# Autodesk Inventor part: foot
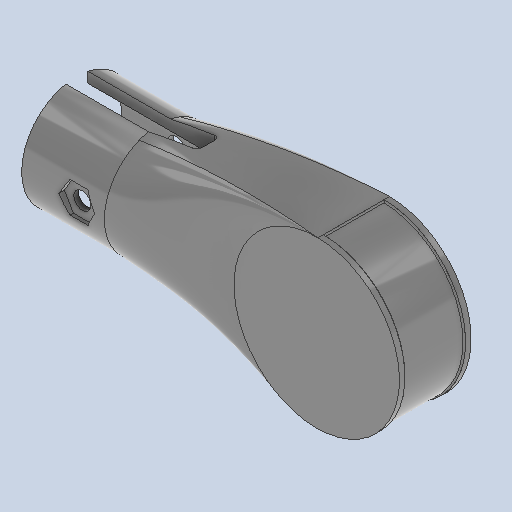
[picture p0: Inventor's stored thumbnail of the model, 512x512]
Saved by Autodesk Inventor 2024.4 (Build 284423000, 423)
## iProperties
Created: 2026-01
Part Number: foot
Material: Generic
Document SubType Name: Modeling
Designer: AdminForWorker
Density: 1 g/cm^3
Appearance: Default
Title: foot
Author: AdminForWorker
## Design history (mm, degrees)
feature "Body1"
body "Solid1"
